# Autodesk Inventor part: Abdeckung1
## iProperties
Shininess: 25.0
Length Units: 11269
Angle Units: 11279
Time Units: 11290
Mass Units: 11283
Length Display Precision: 3
Angle Display Precision: 2
Part Number: Abdeckung1
Material: Standard
Document SubType Name: Blech
Created: 2003-06
Designer: swi
Density: 0.0
Volumn: 0.0
Area: 0.0
PropertySet Name: Model Information
Control State: 0
Master: False
Checked Out: False
Checked Out By: swi
Checked Out Date: 2003-06-27
Author: swi
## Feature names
1. Platte1
2. Platte2
3. Biegung1
4. Platte3
5. Biegung2
6. Platte4
7. Biegung3
8. Platte5
9. Biegung4
10. Platte6
11. Biegung5
12. Platte7
13. Biegung6
14. Platte8
15. Biegung7
16. Platte9
17. Biegung8
18. ExtrusionAbwicklung1
19. Ecke1
20. Ecke2
21. Ecke3
22. Ecke4
23. Ecke5
24. Ecke6
25. Ecke7
26. Ecke8
